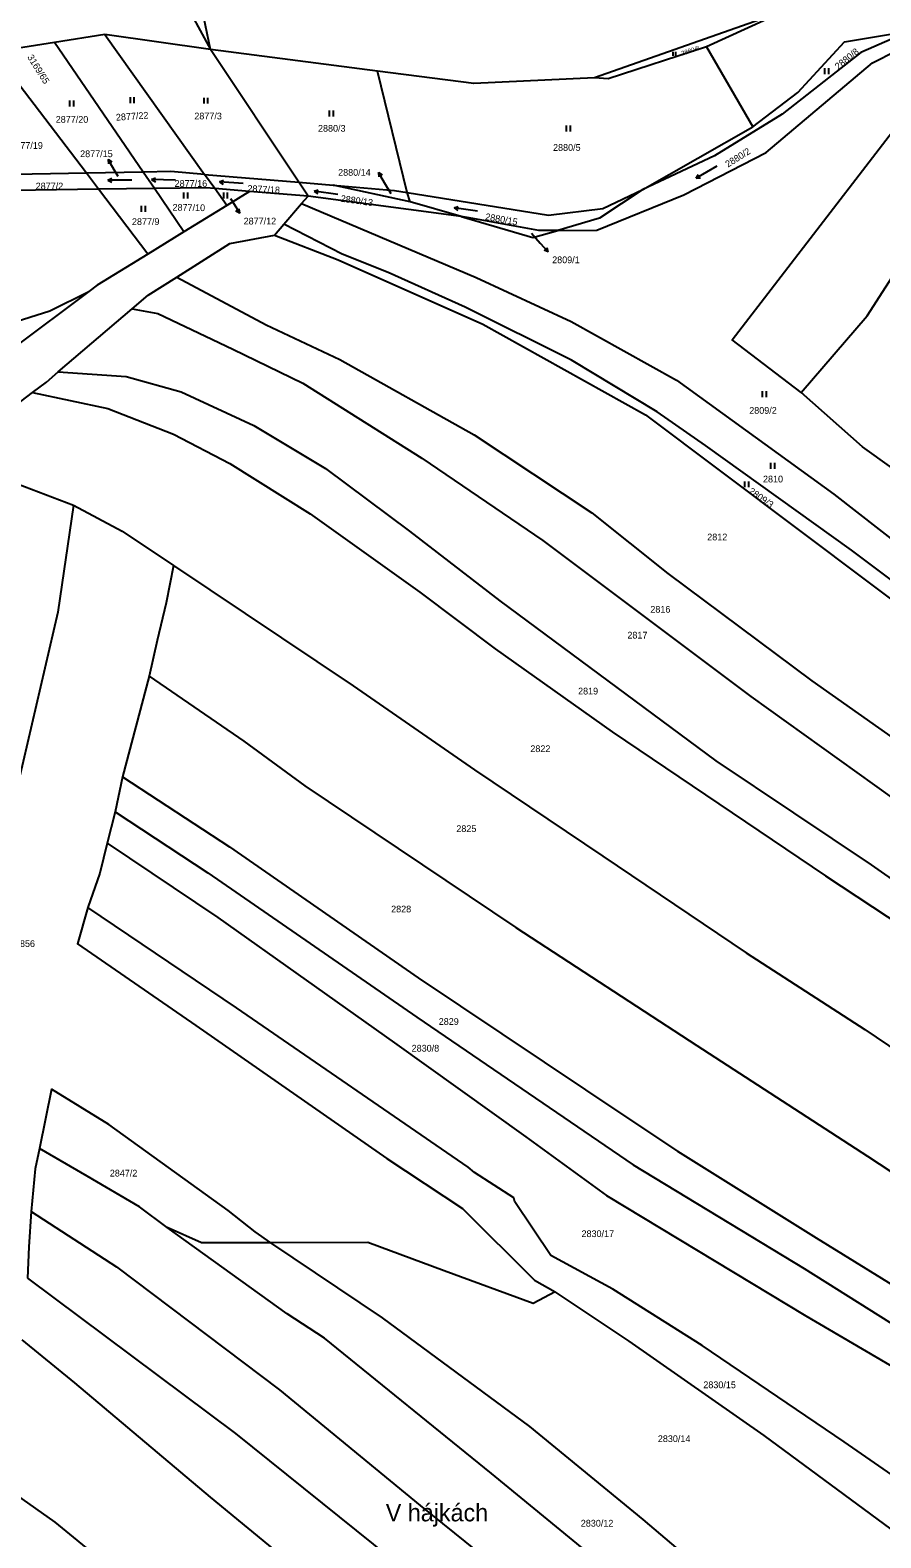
# Model space of a CAD drawing. Extents: x -776734 to -748832, y -1118122 to -976986.
# Drawn here: x -754042.2 to -753827.4, y -1114826.1 to -1114445.3 of the extents above; entities that cross this region are included whole.
import ezdxf

# ---------------------------------------------------------------- set-up
doc = ezdxf.new("R2010")
doc.units = 0
for name, color, linetype in [('KM_Hranice parcel', 7, 'Continuous'), ('KM_Parcelní čísla', 7, 'Continuous'), ('KM_Pop  PČ popisy', 7, 'Continuous'), ('KM_Značky kultur', 7, 'Continuous')]:
    doc.layers.add(name, color=color, linetype=linetype)

msp = doc.modelspace()

# ---------------------------------------------------------------- linework, layer by layer
at = {"layer": 'KM_Hranice parcel'}
for p, q in [((-754016.29, -1114413.97), (-753996.7, -1114450.26)), ((-754023.35, -1114446.44), (-754036.09, -1114448.45)), ((-754023.35, -1114446.44), (-753998.16, -1114481.76)), ((-753996.7, -1114450.26), (-754023.35, -1114446.44)), ((-754036.09, -1114448.45), (-754045.64, -1114449.97)), ((-754013.68, -1114481.19), (-754036.09, -1114448.45)), ((-753954.5, -1114455.67), (-753996.7, -1114450.26)), ((-753974.41, -1114483.76), (-753996.7, -1114450.26)), ((-753871.41, -1114449.57), (-753859.71, -1114469.75)), ((-754028.02, -1114481.47), (-754046.3, -1114457.41)), ((-753947, -1114486.33), (-753954.5, -1114455.67)), ((-753887.55, -1114485.61), (-753859.71, -1114469.75)), ((-754028.02, -1114481.47), (-754058.82, -1114482.07)), ((-754013.68, -1114481.19), (-754028.02, -1114481.47)), ((-754024.94, -1114485.52), (-754028.02, -1114481.47)), ((-754010.85, -1114485.33), (-754013.68, -1114481.19)), ((-753998.16, -1114481.76), (-753974.41, -1114483.76)), ((-753995.61, -1114485.34), (-753998.16, -1114481.76)), ((-754010.85, -1114485.33), (-754024.94, -1114485.52)), ((-754012.51, -1114501.88), (-754024.94, -1114485.52)), ((-754003.37, -1114496.26), (-754010.85, -1114485.33)), ((-753986.8, -1114486.06), (-753995.61, -1114485.34)), ((-753992.57, -1114489.61), (-753995.61, -1114485.34)), ((-753972.02, -1114487.24), (-753974.41, -1114483.76)), ((-753974.41, -1114483.76), (-753965.71, -1114484.5)), ((-753946.25, -1114488.68), (-753965.71, -1114484.5)), ((-753992.57, -1114489.61), (-754003.37, -1114496.26)), ((-753986.8, -1114486.06), (-753992.57, -1114489.61)), ((-753972.02, -1114487.24), (-753986.8, -1114486.06)), ((-753978.14, -1114494.33), (-753973.67, -1114489.15)), ((-753973.67, -1114489.15), (-753972.02, -1114487.24)), ((-753933.36, -1114492.43), (-753972.02, -1114487.24)), ((-753946.25, -1114488.68), (-753947, -1114486.33)), ((-753933.36, -1114492.43), (-753946.25, -1114488.68)), ((-754003.37, -1114496.26), (-754012.51, -1114501.88)), ((-753980.54, -1114497.11), (-753978.14, -1114494.33)), ((-754037.22, -1114516.18), (-754027.41, -1114511.32)), ((-754069.39, -1114526.49), (-754037.22, -1114516.18)), ((-754035.11, -1114531.65), (-754016.44, -1114515.73)), ((-754050.27, -1114543.38), (-754041.64, -1114536.87)), ((-754045.38, -1114559.88), (-754031.22, -1114565.25)), ((-754012.15, -1114608.47), (-754018.86, -1114633.9)), ((-754018.86, -1114633.9), (-754020.76, -1114642.73)), ((-754020.76, -1114642.73), (-754022.72, -1114650.6)), ((-754036.85, -1114712.74), (-754039.88, -1114727.7)), ((-754039.88, -1114727.7), (-754040.92, -1114732.87)), ((-754040.92, -1114732.87), (-754041.97, -1114743.62))]:
    msp.add_line(p, q, dxfattribs=at)
for points in [[(-753996.7, -1114450.26), (-754000.87, -1114429.93), (-754009.28, -1114408.18), (-753999.04, -1114410.93), (-753988.31, -1114406.51), (-753989.59, -1114399.07), (-754018.22, -1114397.62)], [(-753853.36, -1114440.1), (-753857.8, -1114442.65), (-753899.76, -1114457.35)], [(-753853.36, -1114440.1), (-753856.15, -1114442.6), (-753871.41, -1114449.57)], [(-753819.96, -1114445.47), (-753832.52, -1114451.01), (-753852.35, -1114466.52), (-753869.4, -1114477.08), (-753887.55, -1114485.61)], [(-753859.71, -1114469.75), (-753848.36, -1114461.08), (-753836.59, -1114448.28), (-753819.96, -1114445.47)], [(-753908.97, -1114495.91), (-753899.12, -1114495.87), (-753877.2, -1114486.91), (-753856.39, -1114476.24), (-753829.52, -1114453.58), (-753823.57, -1114450.57), (-753807.29, -1114448.61)], [(-753871.41, -1114449.57), (-753896.24, -1114457.62), (-753899.76, -1114457.35)], [(-753847.52, -1114536.86), (-753864.94, -1114523.57), (-753807.29, -1114448.61)], [(-753847.52, -1114536.86), (-753830.91, -1114517.45), (-753786.77, -1114448.95)], [(-753899.76, -1114457.35), (-753930.19, -1114458.78), (-753954.5, -1114455.67)], [(-753998.16, -1114481.76), (-754006.66, -1114481.05), (-754013.68, -1114481.19)], [(-754024.94, -1114485.52), (-754046.18, -1114485.81), (-754059.94, -1114486.92)], [(-753995.61, -1114485.34), (-753997.86, -1114485.16), (-754010.85, -1114485.33)], [(-753965.71, -1114484.5), (-753950.25, -1114485.81), (-753947, -1114486.33)], [(-753947, -1114486.33), (-753911.34, -1114492.07), (-753897.65, -1114490.36), (-753887.55, -1114485.61)], [(-753887.55, -1114485.61), (-753898.46, -1114492.8), (-753908.97, -1114495.91)], [(-753973.67, -1114489.15), (-753929.61, -1114507.83), (-753905.65, -1114518.9), (-753879.04, -1114533.76), (-753839.34, -1114562.55), (-753792.02, -1114599.36), (-753764.44, -1114621.51)], [(-753933.36, -1114492.43), (-753915.3, -1114497.69), (-753908.97, -1114495.91)], [(-753908.97, -1114495.91), (-753913.75, -1114495.93), (-753931.37, -1114492.7), (-753933.36, -1114492.43)], [(-754005.15, -1114507.68), (-753991.8, -1114499.21), (-753980.54, -1114497.11)], [(-753980.54, -1114497.11), (-753964.46, -1114503.37), (-753927.91, -1114519.59), (-753886.84, -1114542.44), (-753772.24, -1114628.6), (-753766.93, -1114631.73)], [(-753766.3, -1114628.7), (-753776.29, -1114621.4), (-753803.14, -1114599.97), (-753815.6, -1114591.13), (-753834.8, -1114576.63), (-753871.73, -1114550.25), (-753883.91, -1114541.75), (-753905.54, -1114528.64), (-753932.39, -1114515.25), (-753951.79, -1114506.5), (-753963.41, -1114501.89), (-753978.14, -1114494.33)], [(-754012.51, -1114501.88), (-754025.3, -1114509.74), (-754027.41, -1114511.32)], [(-754016.44, -1114515.73), (-754012.39, -1114512.28), (-754005.15, -1114507.68)], [(-754005.15, -1114507.68), (-753982.58, -1114519.79), (-753964.03, -1114528.47), (-753930.12, -1114547.54), (-753900.4, -1114567.21), (-753881.25, -1114582.51), (-753844.84, -1114609.65), (-753804.64, -1114638.01), (-753772.64, -1114660.8)], [(-754027.41, -1114511.32), (-754046.53, -1114525.65), (-754058.26, -1114528.19)], [(-754016.44, -1114515.73), (-754009.95, -1114516.85), (-753991, -1114525.89), (-753973.33, -1114534.46), (-753943.34, -1114553.41), (-753912.75, -1114574.24), (-753860.27, -1114613.62), (-753788.9, -1114664.79), (-753775.21, -1114673.56)], [(-754041.64, -1114536.87), (-754038.1, -1114534.2), (-754035.11, -1114531.65)], [(-754035.11, -1114531.65), (-754017.95, -1114532.83), (-754004.05, -1114536.71), (-753985.75, -1114545.16), (-753967.67, -1114556.02), (-753946.4, -1114571.84), (-753923.61, -1114589.45), (-753869.1, -1114629.88), (-753829.86, -1114656.07), (-753791.6, -1114682.84), (-753779.01, -1114691.09)], [(-754041.64, -1114536.87), (-754022.57, -1114540.88), (-754006.04, -1114547.32), (-753991.81, -1114554.8), (-753971.54, -1114567.51), (-753943.82, -1114587.27), (-753924.84, -1114601.57), (-753895.28, -1114622.53), (-753841.37, -1114658.87), (-753813.99, -1114676.99), (-753780.9, -1114700.52)], [(-753817.86, -1114560.71), (-753832.02, -1114550.54), (-753847.52, -1114536.86)], [(-754031.22, -1114565.25), (-754035.22, -1114592.34), (-754046.15, -1114639.42), (-754056.12, -1114676.95), (-754060.73, -1114698.43), (-754066.96, -1114743.71), (-754073.19, -1114785.87), (-754080.47, -1114821.2)], [(-754031.22, -1114565.25), (-754018.99, -1114571.85), (-754006.04, -1114580.49)], [(-754006.04, -1114580.49), (-754007.85, -1114589.91), (-754010.1, -1114599.47), (-754012.15, -1114608.47)], [(-754006.04, -1114580.49), (-753960.65, -1114610.89), (-753930.04, -1114632.09), (-753897.65, -1114653.96), (-753861.39, -1114678.36), (-753831.44, -1114697.72), (-753787.25, -1114727.57)], [(-754012.15, -1114608.47), (-753988.26, -1114624.88), (-753972.82, -1114636.12), (-753919.58, -1114671.95), (-753873.88, -1114701.73), (-753830.77, -1114729.66), (-753793.03, -1114754.47)], [(-754018.86, -1114633.9), (-753991.84, -1114651.56), (-753944.26, -1114684.67), (-753891.31, -1114720.08), (-753878.77, -1114728.45), (-753843.79, -1114750.33), (-753817.6, -1114766.43), (-753797.22, -1114778.89)], [(-754020.76, -1114642.73), (-753997.37, -1114658.12), (-753944.57, -1114694.55), (-753889.95, -1114731.89), (-753846.8, -1114758.03), (-753822.32, -1114773.42), (-753799.4, -1114786.94)], [(-754022.72, -1114650.6), (-754024.6, -1114658.19), (-754027.62, -1114666.84)], [(-754022.72, -1114650.6), (-753994.83, -1114669.44), (-753950.22, -1114701.08), (-753917.06, -1114724.81), (-753896.72, -1114739.61), (-753846.36, -1114769.99), (-753801.69, -1114796.2)], [(-754027.62, -1114666.84), (-754030.25, -1114676.07), (-754000.36, -1114696.65), (-753952.15, -1114730.28), (-753933.07, -1114742.92), (-753914.83, -1114761.01), (-753909.62, -1114763.9)], [(-753806.92, -1114822.44), (-753836.67, -1114801.81), (-753872.53, -1114777.48), (-753895.08, -1114763.26), (-753910.75, -1114754.73), (-753919.85, -1114741.17), (-753920.09, -1114740.22), (-753930, -1114733.83), (-753931.58, -1114732.41), (-753990.09, -1114692.21), (-754027.62, -1114666.84)], [(-753981.41, -1114751.55), (-753985.42, -1114748.81), (-753992.24, -1114743.41), (-754022.32, -1114721.67), (-754036.85, -1114712.74)], [(-754007.59, -1114747.71), (-754014.64, -1114742.5), (-754027.79, -1114734.7), (-754039.88, -1114727.7)], [(-754041.97, -1114743.62), (-754042.51, -1114752.53), (-754042.84, -1114760.47)], [(-754041.97, -1114743.62), (-754020.4, -1114757.62), (-753979.29, -1114788.68), (-753943.78, -1114817.9), (-753872.64, -1114875.24), (-753849.61, -1114894.28), (-753827.64, -1114913.74)], [(-753981.41, -1114751.55), (-753998.91, -1114751.58), (-754007.59, -1114747.71)], [(-753822.92, -1114896.46), (-753844.96, -1114876.16), (-753869.04, -1114856.34), (-753925.76, -1114809.8), (-753967.86, -1114775.67), (-753977.3, -1114769.5), (-754007.59, -1114747.71)], [(-753909.62, -1114763.9), (-753915.25, -1114766.87), (-753937.67, -1114758.62), (-753956.98, -1114751.5), (-753981.41, -1114751.55)], [(-753818.65, -1114879.63), (-753848.46, -1114854.46), (-753887.44, -1114821.39), (-753916.04, -1114797.97), (-753953.24, -1114770.51), (-753981.41, -1114751.55)], [(-754042.84, -1114760.47), (-753990.38, -1114799.67), (-753951.29, -1114831.07), (-753902.83, -1114871.49), (-753856.19, -1114909.47), (-753831.51, -1114930.07)], [(-753809.79, -1114834.95), (-753856.88, -1114800.2), (-753890.97, -1114776.38), (-753909.62, -1114763.9)], [(-754044.32, -1114776.03), (-754030.98, -1114786.91), (-753996.74, -1114815.81), (-753928.78, -1114871.72), (-753884.71, -1114908.95), (-753867.63, -1114921.23), (-753836.21, -1114948.23)], [(-754049.2, -1114812.72), (-754036.01, -1114822.08), (-754012.74, -1114841.09), (-753983.63, -1114866.72), (-753971.24, -1114876.69), (-753931.67, -1114908.95), (-753885.6, -1114948.11), (-753845.51, -1114982.89)]]:
    msp.add_lwpolyline(points, dxfattribs=at)
at = {"layer": 'KM_Pop  PČ popisy'}
for p, q in [((-754021.03, -1114480.57), (-754022.53, -1114477.971)), ((-754022.53, -1114477.971), (-754021.596, -1114478.588)), ((-754022.53, -1114477.971), (-754022.463, -1114479.089)), ((-754020.02, -1114482.31), (-754021.03, -1114480.57)), ((-753952.75, -1114483.86), (-753954.25, -1114481.261)), ((-753954.25, -1114481.261), (-753953.316, -1114481.878)), ((-753954.25, -1114481.261), (-753954.183, -1114482.379)), ((-753951.09, -1114486.7), (-753952.75, -1114483.86)), ((-753991.62, -1114487.82), (-753990.89, -1114489.01)), ((-753990.89, -1114489.01), (-753989.3, -1114491.555)), ((-753989.3, -1114491.555), (-753990.255, -1114490.971)), ((-753989.3, -1114491.555), (-753989.406, -1114490.44)), ((-753915.6, -1114496.6), (-753913.4, -1114499.09)), ((-753913.4, -1114499.09), (-753911.431, -1114501.355)), ((-753911.431, -1114501.355), (-753912.466, -1114500.928)), ((-753911.431, -1114501.355), (-753911.71, -1114500.271))]:
    msp.add_line(p, q, dxfattribs=at)
at = {"layer": 'KM_Značky kultur'}
for p, q in [((-753879.822, -1114451.83), (-753879.822, -1114450.825)), ((-753879.152, -1114451.83), (-753879.152, -1114450.825)), ((-753841.541, -1114456.44), (-753841.541, -1114454.94)), ((-753840.54, -1114456.44), (-753840.54, -1114454.94)), ((-754016.911, -1114463.8), (-754016.911, -1114462.3)), ((-754015.91, -1114463.8), (-754015.91, -1114462.3)), ((-753998.311, -1114463.9), (-753998.311, -1114462.4)), ((-753997.31, -1114463.9), (-753997.31, -1114462.4)), ((-754032.161, -1114464.61), (-754032.161, -1114463.11)), ((-754031.16, -1114464.61), (-754031.16, -1114463.11)), ((-753966.641, -1114467.16), (-753966.641, -1114465.66)), ((-753965.64, -1114467.16), (-753965.64, -1114465.66)), ((-753906.801, -1114470.9), (-753906.801, -1114469.4)), ((-753905.8, -1114470.9), (-753905.8, -1114469.4)), ((-753868.861, -1114479.681), (-753874.057, -1114482.681)), ((-753874.057, -1114482.681), (-753873.462, -1114481.758)), ((-754022.567, -1114483.191), (-754021.59, -1114482.69)), ((-754016.567, -1114483.191), (-754022.567, -1114483.191)), ((-754022.567, -1114483.191), (-754021.59, -1114483.693)), ((-754011.527, -1114483.089), (-754010.541, -1114482.604)), ((-754005.527, -1114483.193), (-754011.527, -1114483.089)), ((-754011.527, -1114483.089), (-754010.558, -1114483.607)), ((-753994.429, -1114483.671), (-753993.419, -1114483.239)), ((-753988.444, -1114484.09), (-753994.429, -1114483.671)), ((-753994.429, -1114483.671), (-753993.489, -1114484.239)), ((-753970.507, -1114485.982), (-753969.469, -1114485.621)), ((-753874.057, -1114482.681), (-753872.96, -1114482.627)), ((-754003.391, -1114487.86), (-754003.391, -1114486.36)), ((-754002.39, -1114487.86), (-754002.39, -1114486.36)), ((-753993.341, -1114487.85), (-753993.341, -1114486.35)), ((-753992.34, -1114487.85), (-753992.34, -1114486.35)), ((-753964.565, -1114486.817), (-753970.507, -1114485.982)), ((-753970.507, -1114485.982), (-753969.609, -1114486.614)), ((-754014.061, -1114491.21), (-754014.061, -1114489.71)), ((-754013.06, -1114491.21), (-754013.06, -1114489.71)), ((-753935.167, -1114490.212), (-753934.129, -1114489.851)), ((-753929.225, -1114491.047), (-753935.167, -1114490.212)), ((-753935.167, -1114490.212), (-753934.269, -1114490.844)), ((-753857.311, -1114538.02), (-753857.311, -1114536.52)), ((-753856.31, -1114538.02), (-753856.31, -1114536.52)), ((-753855.231, -1114556.09), (-753855.231, -1114554.59)), ((-753854.23, -1114556.09), (-753854.23, -1114554.59)), ((-753861.731, -1114560.77), (-753861.731, -1114559.27)), ((-753860.73, -1114560.77), (-753860.73, -1114559.27))]:
    msp.add_line(p, q, dxfattribs=at)

# ---------------------------------------------------------------- texts
at = {"layer": 'KM_Parcelní čísla'}
for s, height, rotation, p in [('3169/65', 1.7, 302, (-754043.006, -1114452.152)), ('2880/6', 1.14, 18, (-753877.631, -1114451.79)), ('2880/8', 1.7, 39, (-753838.195, -1114455.42)), ('2877/22', 1.7, 4, (-754020.49, -1114468.207)), ('2880/2', 1.7, 32, (-753866.049, -1114480.07)), ('2877/18', 1.7, 357, (-753987.394, -1114486.148)), ('2877/10', 1.7, 359, (-754006.274, -1114490.909)), ('2880/13', 1.7, 351.999997, (-753963.918, -1114488.641)), ('2880/15', 1.7, 349.999997, (-753927.407, -1114493.217)), ('2809/3', 1.7, 325, (-753860.977, -1114562.106))]:
    msp.add_text(s, height=height, rotation=rotation, dxfattribs=at).set_placement(p)
for s, p in [('2877/3', (-754000.76, -1114467.87)), ('2877/20', (-754035.75, -1114468.73)), ('2880/3', (-753969.53, -1114470.98)), ('2877/19', (-754047.22, -1114475.31)), ('2880/5', (-753910.19, -1114475.82)), ('2877/15', (-754029.583, -1114477.41)), ('2880/14', (-753964.453, -1114482.12)), ('2877/2', (-754040.81, -1114485.56)), ('2877/16', (-754005.73, -1114484.91)), ('2877/9', (-754016.51, -1114494.54)), ('2877/12', (-753988.31, -1114494.408)), ('2809/1', (-753910.41, -1114504.188)), ('2809/2', (-753860.66, -1114542.22)), ('2810', (-753857.18, -1114559.55)), ('2812', (-753871.26, -1114574.18)), ('2816', (-753885.62, -1114592.44)), ('2817', (-753891.42, -1114598.96)), ('2819', (-753903.87, -1114613.09)), ('2822', (-753915.92, -1114627.64)), ('2825', (-753934.61, -1114647.83)), ('2828', (-753951.07, -1114668.11)), ('2856', (-754046.05, -1114676.85)), ('2829', (-753939.05, -1114696.52)), ('2830/8', (-753945.89, -1114703.27)), ('2847/2', (-754022.1, -1114734.81)), ('2830/17', (-753903, -1114750.11)), ('2830/15', (-753872.25, -1114788.26)), ('2830/14', (-753883.73, -1114801.87)), ('2830/12', (-753903.18, -1114823.21))]:
    msp.add_text(s, height=1.7, dxfattribs=at).set_placement(p)
at = {"layer": 'KM_Pop  PČ popisy'}
msp.add_text('V hájkách', height=4.4, dxfattribs=at).set_placement((-753952.416, -1114821.89))

doc.saveas('drawing.dxf')
